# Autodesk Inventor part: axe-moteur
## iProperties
Author: robert
Shininess: 20.0
Angle Display Precision: 2
Document Length Units: 11269
Document Angle Units: 11283
Document Time Units: 11279
Document Mass Units: 11290
Document Length Units Precision: 3
Document Angle Units Precision: 2
Compacted: True
PropertySet Name: _Private Model Information
Created: 2002-06
Part Number: axe-moteur
Material: Par défaut
Document SubType Name: Modélisation
Designer: robert
Control State: 0
Master: False
Checked Out: False
PropertySet Name: Design Tracking Control
Density: 0.0
Volumn: 0.0
Area: 0.0
PropertySet Name: Model Information
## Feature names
1. Extrusion1
2. Chanfrein1 [Chamfer]
3. Extrusion2
4. Perçage1 [Hole]
5. Extrusion4
